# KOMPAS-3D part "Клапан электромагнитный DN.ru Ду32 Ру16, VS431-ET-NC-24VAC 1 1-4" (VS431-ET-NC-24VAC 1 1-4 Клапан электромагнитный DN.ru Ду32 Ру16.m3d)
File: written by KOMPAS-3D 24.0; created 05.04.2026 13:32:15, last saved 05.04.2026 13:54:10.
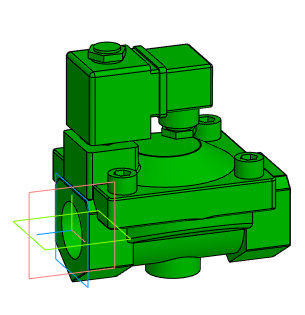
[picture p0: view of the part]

Document properties: Автор: artio; Полное имя файла: C:\Users\artio\OneDrive\Рабочий стол\Клапан электромагнитный DN.ru\VS431\VS431-ET-NC\VS431-ET-NC-24VAC\Ду32\VS431-ET-NC-24VAC 1 1-4 Клапан электромагнитный DN.ru Ду32 Ру16.m3d

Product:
- Body: Тело 1  | qty 1
    Масса: 3.709873
- Part/product: Клапан электромагнитный DN.ru Ду32 Ру16  | designation VS431-ET-NC-24VAC 1 1-4
    Масса: 1.701
    Раздел спецификации: Прочие изделия
    Примечание: D130-05505
    additional columns: ef56311e-7521-43dc-8291-0e6108b3d81d; artio; c; Шероховатость не задана; Да

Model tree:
1. Операция без истории:1

Expressions: VS431-ET-NC-24VAC 1 1-4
